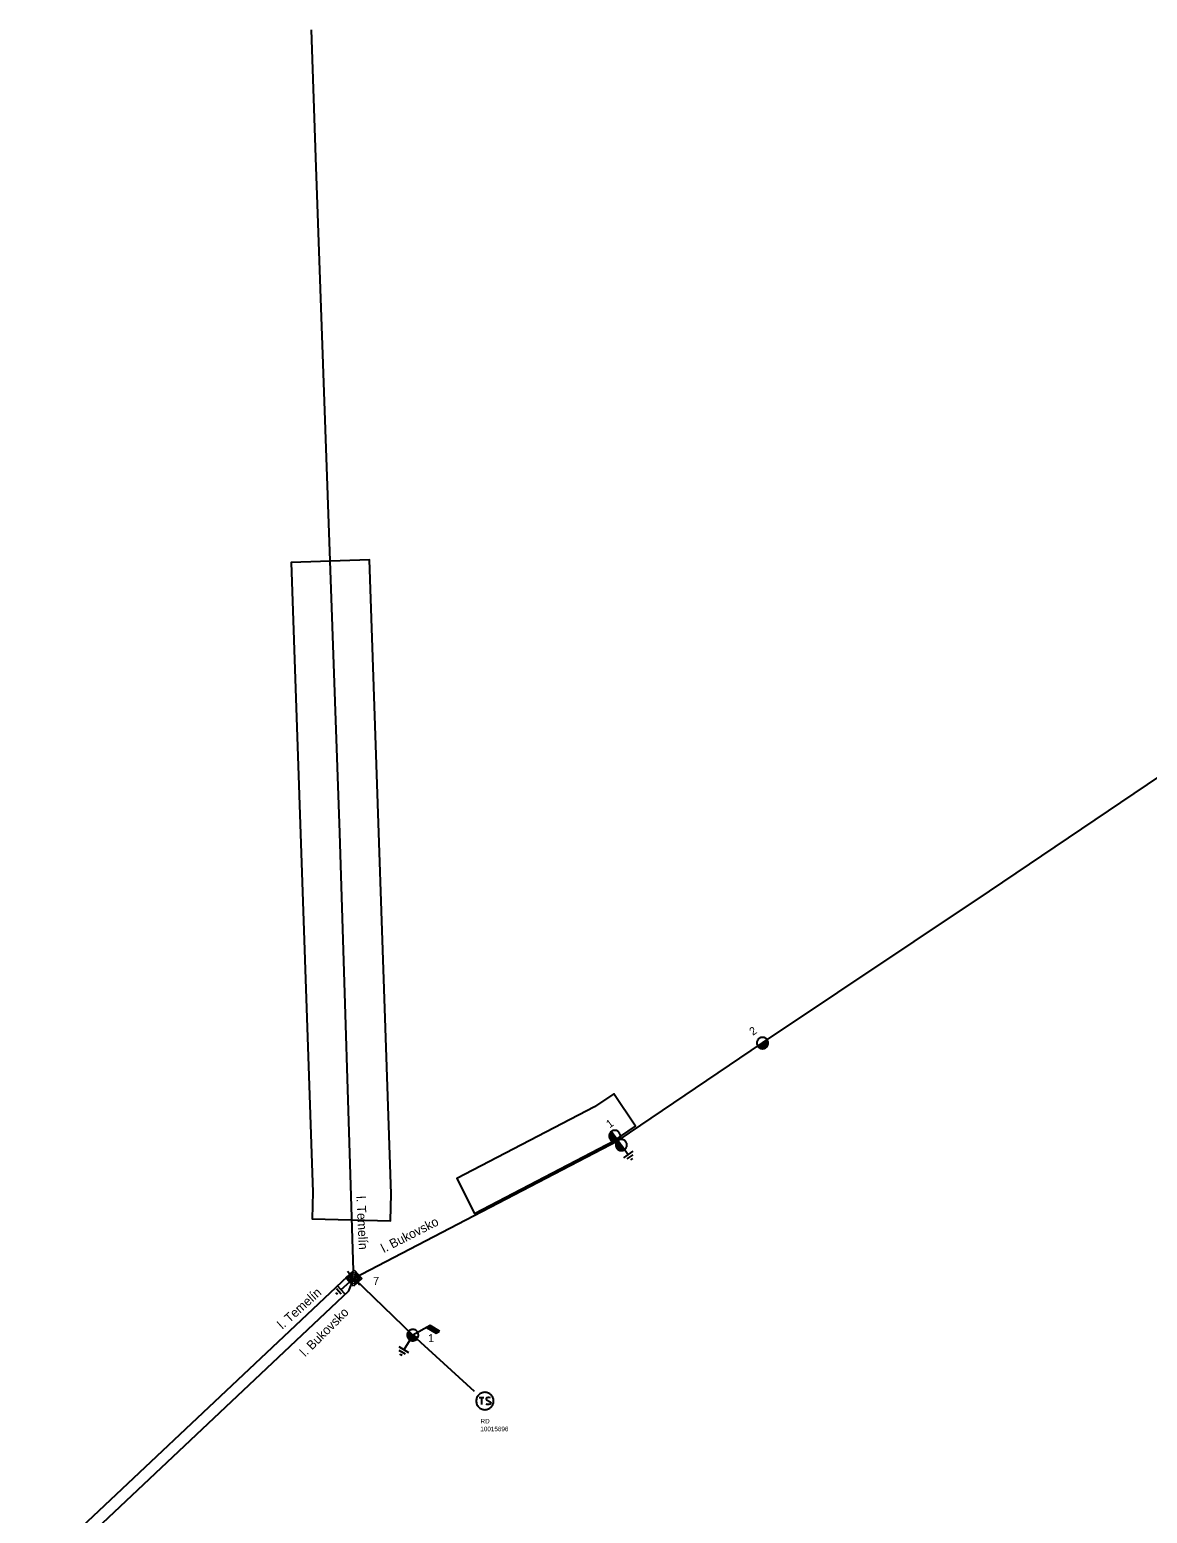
# Model space of a CAD drawing. Extents: x -762500 to -761250, y -1153000 to -1152000.
# Drawn here: x -761886.4 to -761643.3, y -1152322.5 to -1152000 of the extents above; entities that cross this region are included whole.
import ezdxf

# ---------------------------------------------------------------- set-up
doc = ezdxf.new("R2010")
doc.units = 0
for name, color, linetype in [('Vrstva 1', 7, 'Continuous'), ('Vrstva 11', 7, 'Continuous'), ('Vrstva 13', 7, 'Continuous'), ('Vrstva 14', 7, 'Continuous'), ('Vrstva 15', 7, 'Continuous'), ('Vrstva 25', 7, 'Continuous'), ('Vrstva 26', 7, 'Continuous'), ('Vrstva 27', 7, 'Continuous'), ('Vrstva 3', 7, 'Continuous'), ('Vrstva 35', 7, 'Continuous'), ('Vrstva 4', 7, 'Continuous')]:
    doc.layers.add(name, color=color, linetype=linetype)

msp = doc.modelspace()

# ---------------------------------------------------------------- linework, layer by layer
at = {"layer": 'Vrstva 1'}
for points in [[(-761815.94, -1152269.79), (-761818.9, -1152174.57), (-761824.11, -1152027.78), (-761825.1, -1152000)], [(-761727.01, -1152220.29), (-761677.68, -1152187.28), (-761586, -1152125.42), (-761497.64, -1152065.71), (-761400.34, -1152000)], [(-761815.89, -1152271.42), (-761758.42, -1152241.49), (-761727.01, -1152220.29)], [(-762207.96, -1152637.64), (-762154.45, -1152587.37), (-762076.76, -1152514.45), (-761980.31, -1152424.19), (-761895.21, -1152344.48), (-761815.94, -1152269.79)], [(-762206.29, -1152639.5), (-762152.73, -1152589.19), (-762075.04, -1152516.27), (-761978.61, -1152426.01), (-761893.49, -1152346.3), (-761816.97, -1152274.17), (-761815.89, -1152271.42)]]:
    msp.add_lwpolyline(points, dxfattribs=at)
at = {"layer": 'Vrstva 11'}
for p, q in [((-761800.005, -1152282.093), (-761797.937, -1152283.335)), ((-761799.955, -1152282.065), (-761797.887, -1152283.307)), ((-761799.905, -1152282.037), (-761797.836, -1152283.279)), ((-761799.854, -1152282.009), (-761797.786, -1152283.251)), ((-761799.804, -1152281.981), (-761797.736, -1152283.223)), ((-761799.754, -1152281.952), (-761797.685, -1152283.195)), ((-761799.704, -1152281.924), (-761797.635, -1152283.167)), ((-761799.653, -1152281.896), (-761797.584, -1152283.139)), ((-761799.603, -1152281.868), (-761797.534, -1152283.111)), ((-761799.553, -1152281.84), (-761797.483, -1152283.083)), ((-761799.503, -1152281.812), (-761797.433, -1152283.055)), ((-761799.452, -1152281.784), (-761797.382, -1152283.027)), ((-761799.402, -1152281.755), (-761797.332, -1152283)), ((-761799.352, -1152281.727), (-761797.281, -1152282.972)), ((-761799.302, -1152281.699), (-761798.949, -1152281.911))]:
    msp.add_line(p, q, dxfattribs=at)
msp.add_lwpolyline([(-761799.301, -1152281.699), (-761803.05, -1152283.8)], dxfattribs=at)
msp.add_lwpolyline([(-761797.235, -1152282.946), (-761799.301, -1152281.699), (-761800.052, -1152282.12), (-761797.984, -1152283.361)], close=True, dxfattribs=at)
at = {"layer": 'Vrstva 13'}
for points in [[(-761726.022, -1152219.576), (-761726.103, -1152219.476), (-761726.194, -1152219.385), (-761726.294, -1152219.304), (-761726.402, -1152219.234), (-761726.516, -1152219.176), (-761726.636, -1152219.13), (-761726.76, -1152219.097), (-761726.887, -1152219.076), (-761727.015, -1152219.069), (-761727.144, -1152219.076), (-761727.271, -1152219.096), (-761727.395, -1152219.13), (-761727.515, -1152219.176), (-761727.63, -1152219.234), (-761727.738, -1152219.304), (-761727.837, -1152219.385), (-761727.928, -1152219.476), (-761728.01, -1152219.576), (-761728.079, -1152219.684), (-761728.138, -1152219.798), (-761728.184, -1152219.918), (-761728.217, -1152220.043), (-761728.237, -1152220.17), (-761728.244, -1152220.298), (-761728.237, -1152220.426), (-761728.217, -1152220.553), (-761728.184, -1152220.678), (-761728.138, -1152220.798), (-761728.08, -1152220.912), (-761728.009, -1152221.02), (-761727.929, -1152221.12), (-761727.838, -1152221.211), (-761727.738, -1152221.292), (-761727.629, -1152221.362), (-761727.515, -1152221.42), (-761727.395, -1152221.466), (-761727.271, -1152221.5), (-761727.144, -1152221.52), (-761727.016, -1152221.526), (-761726.887, -1152221.52), (-761726.76, -1152221.5), (-761726.636, -1152221.466), (-761726.516, -1152221.42), (-761726.401, -1152221.362), (-761726.294, -1152221.292), (-761726.194, -1152221.211), (-761726.103, -1152221.12), (-761726.022, -1152221.02), (-761725.952, -1152220.912), (-761725.893, -1152220.798), (-761725.847, -1152220.678), (-761725.814, -1152220.553), (-761725.794, -1152220.426), (-761725.787, -1152220.298), (-761725.794, -1152220.17), (-761725.814, -1152220.043), (-761725.848, -1152219.919), (-761725.894, -1152219.798), (-761725.952, -1152219.684), (-761726.022, -1152219.576)], [(-761728.017, -1152221.016), (-761726.029, -1152219.572)], [(-761727.767, -1152221.261), (-761725.92, -1152219.919)], [(-761727.458, -1152221.393), (-761725.859, -1152220.231)], [(-761727.071, -1152221.468), (-761725.923, -1152220.633)], [(-761758.419, -1152241.49), (-761758.321, -1152241.41), (-761758.231, -1152241.32), (-761758.15, -1152241.221), (-761758.081, -1152241.114), (-761758.023, -1152241), (-761757.977, -1152240.881), (-761757.944, -1152240.757), (-761757.924, -1152240.632), (-761757.918, -1152240.504), (-761757.924, -1152240.377), (-761757.944, -1152240.251), (-761757.977, -1152240.128), (-761758.023, -1152240.008), (-761758.081, -1152239.895), (-761758.151, -1152239.788), (-761758.231, -1152239.689), (-761758.32, -1152239.599), (-761758.42, -1152239.519), (-761758.527, -1152239.449), (-761758.641, -1152239.391), (-761758.76, -1152239.345), (-761758.883, -1152239.312), (-761759.009, -1152239.292), (-761759.136, -1152239.286), (-761759.264, -1152239.292), (-761759.39, -1152239.313), (-761759.513, -1152239.345), (-761759.632, -1152239.391), (-761759.745, -1152239.449), (-761759.853, -1152239.519), (-761759.952, -1152239.599), (-761760.042, -1152239.689), (-761760.122, -1152239.788), (-761760.192, -1152239.895), (-761760.25, -1152240.009), (-761760.295, -1152240.128), (-761760.328, -1152240.251), (-761760.348, -1152240.377), (-761760.355, -1152240.504), (-761760.348, -1152240.632), (-761760.328, -1152240.758), (-761760.295, -1152240.881), (-761760.25, -1152241), (-761760.192, -1152241.113), (-761760.122, -1152241.221), (-761760.042, -1152241.32), (-761759.952, -1152241.41), (-761759.853, -1152241.49), (-761759.745, -1152241.56), (-761759.632, -1152241.618), (-761759.513, -1152241.663), (-761759.389, -1152241.696), (-761759.264, -1152241.716), (-761759.136, -1152241.723), (-761759.009, -1152241.716), (-761758.883, -1152241.696), (-761758.76, -1152241.663), (-761758.64, -1152241.618), (-761758.527, -1152241.56), (-761758.42, -1152241.491)], [(-761760.349, -1152240.402), (-761759.413, -1152241.69)], [(-761760.248, -1152240.019), (-761759.018, -1152241.712)], [(-761760.078, -1152239.73), (-761758.691, -1152241.639)], [(-761759.852, -1152239.518), (-761756.987, -1152243.462)], [(-761756.987, -1152243.462), (-761756.888, -1152243.382), (-761756.798, -1152243.292), (-761756.718, -1152243.193), (-761756.648, -1152243.086), (-761756.59, -1152242.972), (-761756.545, -1152242.853), (-761756.511, -1152242.729), (-761756.492, -1152242.604), (-761756.485, -1152242.476), (-761756.492, -1152242.349), (-761756.512, -1152242.223), (-761756.545, -1152242.1), (-761756.59, -1152241.98), (-761756.648, -1152241.867), (-761756.718, -1152241.76), (-761756.798, -1152241.661), (-761756.888, -1152241.571), (-761756.987, -1152241.49), (-761757.095, -1152241.421), (-761757.208, -1152241.363), (-761757.327, -1152241.317), (-761757.45, -1152241.284), (-761757.576, -1152241.264), (-761757.703, -1152241.258), (-761757.831, -1152241.264), (-761757.957, -1152241.284), (-761758.08, -1152241.317), (-761758.199, -1152241.363), (-761758.313, -1152241.421), (-761758.42, -1152241.491), (-761758.519, -1152241.571), (-761758.609, -1152241.66), (-761758.689, -1152241.76), (-761758.759, -1152241.867), (-761758.817, -1152241.981), (-761758.862, -1152242.1), (-761758.896, -1152242.223), (-761758.915, -1152242.349), (-761758.922, -1152242.476), (-761758.915, -1152242.604), (-761758.895, -1152242.73), (-761758.862, -1152242.853), (-761758.817, -1152242.972), (-761758.759, -1152243.085), (-761758.689, -1152243.193), (-761758.609, -1152243.292), (-761758.519, -1152243.382), (-761758.42, -1152243.462), (-761758.312, -1152243.532), (-761758.199, -1152243.59), (-761758.08, -1152243.635), (-761757.957, -1152243.668), (-761757.831, -1152243.688), (-761757.703, -1152243.695), (-761757.576, -1152243.688), (-761757.45, -1152243.668), (-761757.327, -1152243.635), (-761757.208, -1152243.59), (-761757.094, -1152243.532), (-761756.987, -1152243.463)], [(-761758.815, -1152241.991), (-761757.585, -1152243.684)], [(-761758.645, -1152241.702), (-761757.258, -1152243.611)], [(-761758.916, -1152242.374), (-761757.98, -1152243.662)], [(-761817.623, -1152271.362), (-761815.826, -1152269.687)], [(-761816.724, -1152270.525), (-761817.234, -1152269.977)], [(-761817.175, -1152271.392), (-761815.828, -1152270.135)], [(-761816.755, -1152271.393), (-761815.856, -1152270.555)], [(-761816.347, -1152271.38), (-761815.897, -1152270.961)], [(-761815.897, -1152270.961), (-761815.479, -1152271.41)], [(-761815.856, -1152270.555), (-761815.018, -1152271.454)], [(-761815.828, -1152270.135), (-761814.571, -1152271.483)], [(-761815.826, -1152269.687), (-761814.15, -1152271.484)], [(-761815.947, -1152273.159), (-761817.623, -1152271.362)], [(-761815.919, -1152272.739), (-761817.175, -1152271.392)], [(-761815.917, -1152272.291), (-761816.755, -1152271.393)], [(-761815.928, -1152271.829), (-761816.347, -1152271.38)], [(-761814.15, -1152271.484), (-761815.947, -1152273.159)], [(-761815.479, -1152271.41), (-761815.928, -1152271.829)], [(-761814.571, -1152271.483), (-761815.919, -1152272.739)], [(-761815.018, -1152271.454), (-761815.917, -1152272.291)], [(-761815.049, -1152272.322), (-761814.538, -1152272.869)], [(-761802.007, -1152284.431), (-761801.947, -1152284.318), (-761801.899, -1152284.199), (-761801.863, -1152284.075), (-761801.84, -1152283.948), (-761801.832, -1152283.82), (-761801.836, -1152283.692), (-761801.854, -1152283.564), (-761801.885, -1152283.44), (-761801.929, -1152283.319), (-761801.986, -1152283.203), (-761802.053, -1152283.094), (-761802.133, -1152282.993), (-761802.222, -1152282.9), (-761802.321, -1152282.818), (-761802.427, -1152282.746), (-761802.54, -1152282.685), (-761802.66, -1152282.637), (-761802.784, -1152282.602), (-761802.91, -1152282.579), (-761803.038, -1152282.57), (-761803.167, -1152282.575), (-761803.294, -1152282.593), (-761803.419, -1152282.624), (-761803.54, -1152282.668), (-761803.655, -1152282.724), (-761803.764, -1152282.792), (-761803.866, -1152282.871), (-761803.958, -1152282.961), (-761804.041, -1152283.059), (-761804.113, -1152283.166), (-761804.173, -1152283.28), (-761804.221, -1152283.399), (-761804.257, -1152283.522), (-761804.279, -1152283.649), (-761804.288, -1152283.777), (-761804.284, -1152283.905), (-761804.266, -1152284.033), (-761804.235, -1152284.158), (-761804.191, -1152284.279), (-761804.134, -1152284.394), (-761804.066, -1152284.503), (-761803.987, -1152284.604), (-761803.898, -1152284.697), (-761803.799, -1152284.78), (-761803.693, -1152284.851), (-761803.579, -1152284.912), (-761803.46, -1152284.96), (-761803.336, -1152284.995), (-761803.21, -1152285.018), (-761803.082, -1152285.027), (-761802.953, -1152285.023), (-761802.825, -1152285.005), (-761802.701, -1152284.973), (-761802.58, -1152284.929), (-761802.464, -1152284.873), (-761802.355, -1152284.805), (-761802.254, -1152284.726), (-761802.162, -1152284.636), (-761802.079, -1152284.538), (-761802.007, -1152284.431)], [(-761804.241, -1152283.819), (-761802.546, -1152284.837)], [(-761804.24, -1152283.483), (-761802.282, -1152284.659)], [(-761804.158, -1152284.204), (-761802.941, -1152284.936)], [(-761804.112, -1152283.157), (-761802.006, -1152284.423)]]:
    msp.add_lwpolyline(points, dxfattribs=at)
at = {"layer": 'Vrstva 15'}
for points in [[(-761757.684, -1152242.497), (-761756.215, -1152244.519)], [(-761755.204, -1152243.784), (-761757.226, -1152245.254)], [(-761755.229, -1152244.57), (-761756.503, -1152245.495)], [(-761755.265, -1152245.374), (-761755.48, -1152245.53)], [(-761755.48, -1152245.53), (-761755.687, -1152245.681)], [(-761818.619, -1152274.915), (-761819.673, -1152273.745)], [(-761817.835, -1152274.859), (-761819.508, -1152273.001)], [(-761816.814, -1152272.257), (-761818.672, -1152273.93)], [(-761819.601, -1152274.766), (-761819.772, -1152274.576)], [(-761819.423, -1152274.964), (-761819.601, -1152274.766)], [(-761803.906, -1152287.658), (-761806.048, -1152286.37)], [(-761804.638, -1152287.941), (-761805.988, -1152287.13)], [(-761803.689, -1152284.871), (-761804.977, -1152287.014)], [(-761805.621, -1152288.085), (-761805.84, -1152287.954)], [(-761805.393, -1152288.222), (-761805.621, -1152288.085)]]:
    msp.add_lwpolyline(points, dxfattribs=at)
at = {"layer": 'Vrstva 25'}
for points in [[(-761785.487, -1152298.121), (-761785.498, -1152297.924), (-761785.529, -1152297.728), (-761785.58, -1152297.537), (-761785.651, -1152297.352), (-761785.741, -1152297.177), (-761785.849, -1152297.011), (-761785.973, -1152296.857), (-761786.113, -1152296.717), (-761786.267, -1152296.593), (-761786.433, -1152296.485), (-761786.609, -1152296.395), (-761786.793, -1152296.324), (-761786.984, -1152296.273), (-761787.18, -1152296.242), (-761787.377, -1152296.231), (-761787.575, -1152296.242), (-761787.771, -1152296.273), (-761787.961, -1152296.324), (-761788.147, -1152296.395), (-761788.322, -1152296.485), (-761788.488, -1152296.593), (-761788.642, -1152296.717), (-761788.782, -1152296.857), (-761788.906, -1152297.011), (-761789.014, -1152297.177), (-761789.104, -1152297.352), (-761789.175, -1152297.537), (-761789.226, -1152297.728), (-761789.257, -1152297.924), (-761789.268, -1152298.121), (-761789.257, -1152298.319), (-761789.226, -1152298.515), (-761789.175, -1152298.705), (-761789.104, -1152298.89), (-761789.014, -1152299.066), (-761788.906, -1152299.232), (-761788.781, -1152299.386), (-761788.642, -1152299.525), (-761788.488, -1152299.65), (-761788.322, -1152299.758), (-761788.146, -1152299.848), (-761787.961, -1152299.919), (-761787.771, -1152299.97), (-761787.575, -1152300.001), (-761787.377, -1152300.012), (-761787.18, -1152300.001), (-761786.984, -1152299.97), (-761786.793, -1152299.919), (-761786.609, -1152299.848), (-761786.433, -1152299.758), (-761786.267, -1152299.65), (-761786.113, -1152299.525), (-761785.973, -1152299.386), (-761785.849, -1152299.232), (-761785.741, -1152299.066), (-761785.651, -1152298.89), (-761785.58, -1152298.705), (-761785.529, -1152298.515), (-761785.498, -1152298.319), (-761785.487, -1152298.121)], [(-761788.639, -1152297.338), (-761787.631, -1152297.338)], [(-761788.135, -1152297.338), (-761788.135, -1152298.912)], [(-761786.182, -1152297.464), (-761786.434, -1152297.338), (-761786.749, -1152297.338), (-761787.001, -1152297.464), (-761787.127, -1152297.652), (-761787.127, -1152297.716), (-761787.001, -1152297.904), (-761786.245, -1152298.282), (-761786.119, -1152298.44), (-761786.119, -1152298.598), (-761786.245, -1152298.786), (-761786.497, -1152298.912), (-761786.749, -1152298.912), (-761786.875, -1152298.85), (-761787.127, -1152298.724)]]:
    msp.add_lwpolyline(points, dxfattribs=at)
at = {"layer": 'Vrstva 35'}
for points in [[(-761807.77, -1152253.11), (-761812.5, -1152115.22), (-761829.49, -1152115.82), (-761824.77, -1152252.71), (-761824.91, -1152258.55), (-761807.91, -1152258.95)], [(-761759.16, -1152241.46), (-761754.6, -1152238.39), (-761759.34, -1152231.33), (-761763.51, -1152234.15), (-761793.47, -1152249.75), (-761789.62, -1152257.33)]]:
    msp.add_lwpolyline(points, close=True, dxfattribs=at)
at = {"layer": 'Vrstva 4'}
for points in [[(-761815.89, -1152271.42), (-761803.05, -1152283.8)], [(-761803.05, -1152283.8), (-761789.71, -1152295.98)]]:
    msp.add_lwpolyline(points, dxfattribs=at)

# ---------------------------------------------------------------- texts
at = {"layer": 'Vrstva 14'}
for s, p in [('2', (-761729.11, -1152218.76)), ('1', (-761760.25, -1152238.87))]:
    msp.add_text(s, height=1.74, rotation=35.60523, dxfattribs=at).set_placement(p)
for s, p in [('7', (-761811.67, -1152272.88)), ('1', (-761799.72, -1152285.32))]:
    msp.add_text(s, height=1.74, dxfattribs=at).set_placement(p)
at = {"layer": 'Vrstva 26'}
msp.add_text('10015696', height=0.9943, dxfattribs=at).set_placement((-761788.37, -1152304.7))
at = {"layer": 'Vrstva 27'}
msp.add_text('RD', height=0.9943, dxfattribs=at).set_placement((-761788.33, -1152303))
at = {"layer": 'Vrstva 3'}
for s, height, rotation, p in [('l. Temelín', 1.9886, 272.75836, (-761815.33, -1152253.6)), ('l. Bukovsko', 1.98858, 27.03958, (-761809.34, -1152265.96)), ('l. Temelín', 1.9886, 42, (-761831.41, -1152282.61)), ('l. Bukovsko', 1.98858, 45.00482, (-761826.43, -1152288.63))]:
    msp.add_text(s, height=height, rotation=rotation, dxfattribs=at).set_placement(p)

doc.saveas('drawing.dxf')
